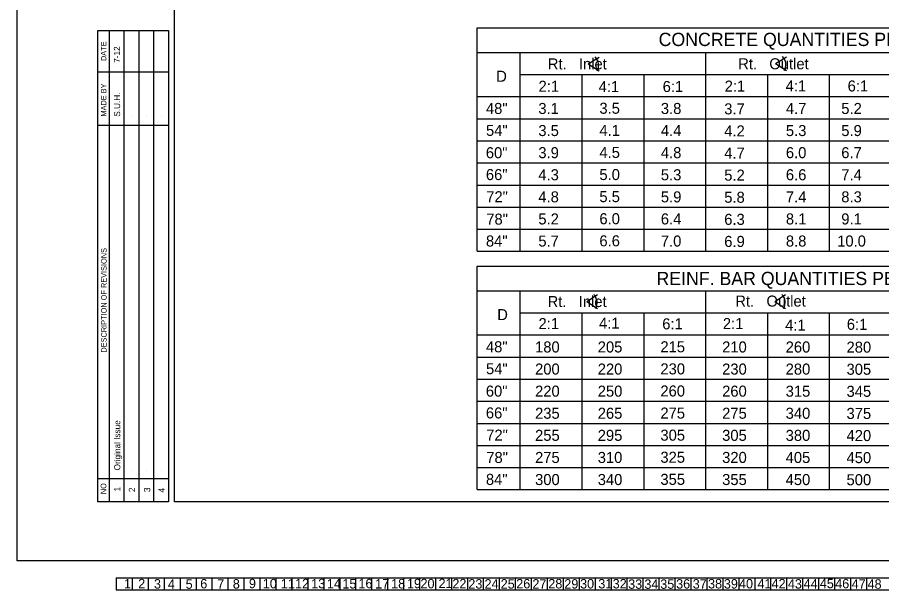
# Model space of a CAD drawing. Extents: x -0.08 to 2.83, y -0.03 to 1.92.
# Drawn here: x 0 to 0.917, y -0.031 to 0.576 of the extents above; entities that cross this region are included whole.
import ezdxf

# ---------------------------------------------------------------- set-up
doc = ezdxf.new("R2010")
doc.units = 0
for name, color, linetype in [('1', 7, 'Continuous'), ('10', 7, 'Continuous'), ('11', 7, 'Continuous'), ('12', 7, 'Continuous'), ('13', 7, 'Continuous'), ('14', 7, 'Continuous'), ('15', 7, 'Continuous'), ('16', 7, 'Continuous'), ('17', 7, 'Continuous'), ('18', 7, 'Continuous'), ('19', 7, 'Continuous'), ('2', 7, 'Continuous'), ('20', 7, 'Continuous'), ('21', 7, 'Continuous'), ('22', 7, 'Continuous'), ('23', 7, 'Continuous'), ('24', 7, 'Continuous'), ('25', 7, 'Continuous'), ('26', 7, 'Continuous'), ('27', 7, 'Continuous'), ('28', 7, 'Continuous'), ('29', 7, 'Continuous'), ('3', 7, 'Continuous'), ('30', 7, 'Continuous'), ('31', 7, 'Continuous'), ('32', 7, 'Continuous'), ('33', 7, 'Continuous'), ('34', 7, 'Continuous'), ('35', 7, 'Continuous'), ('36', 7, 'Continuous'), ('37', 7, 'Continuous'), ('38', 7, 'Continuous'), ('39', 7, 'Continuous'), ('4', 7, 'Continuous'), ('40', 7, 'Continuous'), ('41', 7, 'Continuous'), ('42', 7, 'Continuous'), ('43', 7, 'Continuous'), ('44', 7, 'Continuous'), ('45', 7, 'Continuous'), ('46', 7, 'Continuous'), ('47', 7, 'Continuous'), ('48', 7, 'Continuous'), ('5', 7, 'Continuous'), ('55', 7, 'Continuous'), ('57', 7, 'Continuous'), ('6', 7, 'Continuous'), ('62', 7, 'Continuous'), ('63', 7, 'Continuous'), ('7', 7, 'Continuous'), ('8', 7, 'Continuous'), ('9', 7, 'Continuous')]:
    doc.layers.add(name, color=color, linetype=linetype)

msp = doc.modelspace()

# ---------------------------------------------------------------- linework, layer by layer
at = {"layer": '55'}
for p, q in [((0.48802, 0.32823), (0.48802, 0.56521)), ((0.48802, 0.56521), (1.51802, 0.56521)), ((0.48802, 0.53916), (1.51802, 0.53916)), ((0.53364, 0.32823), (0.53364, 0.53916)), ((0.73052, 0.32823), (0.73052, 0.53916)), ((0.53364, 0.51573), (1.51802, 0.51573)), ((0.59927, 0.32823), (0.59927, 0.51573)), ((0.66489, 0.32823), (0.66489, 0.51573)), ((0.79614, 0.32823), (0.79614, 0.51573)), ((0.86177, 0.32823), (0.86177, 0.51573)), ((0.48802, 0.49229), (1.51802, 0.49229)), ((0.48802, 0.46885), (1.51802, 0.46885)), ((0.48802, 0.44541), (1.51802, 0.44541)), ((0.48802, 0.42198), (1.51802, 0.42198)), ((0.48802, 0.39854), (1.51802, 0.39854)), ((0.48802, 0.3751), (1.51802, 0.3751)), ((0.48802, 0.35166), (1.51802, 0.35166)), ((0.48802, 0.32823), (1.51802, 0.32823)), ((0.48801, 0.07539), (0.48801, 0.31237)), ((0.48801, 0.31237), (1.518, 0.31237)), ((0.48801, 0.28633), (1.518, 0.28633)), ((0.53363, 0.07539), (0.53363, 0.28633)), ((0.7305, 0.07539), (0.7305, 0.28633)), ((0.53363, 0.26289), (1.518, 0.26289)), ((0.59925, 0.07539), (0.59925, 0.26289)), ((0.66488, 0.07539), (0.66488, 0.26289)), ((0.79613, 0.07539), (0.79613, 0.26289)), ((0.86175, 0.07539), (0.86175, 0.26289)), ((0.48801, 0.23945), (1.518, 0.23945)), ((0.48801, 0.21601), (1.518, 0.21601)), ((0.48801, 0.19258), (1.518, 0.19258)), ((0.48801, 0.16914), (1.518, 0.16914)), ((0.48801, 0.1457), (1.518, 0.1457)), ((0.48801, 0.12226), (1.518, 0.12226)), ((0.48801, 0.09883), (1.518, 0.09883)), ((0.48801, 0.07539), (1.518, 0.07539))]:
    msp.add_line(p, q, dxfattribs=at)
at = {"layer": '57'}
for points in [[(0.60568, 0.52691), (0.61719, 0.53429)], [(0.80436, 0.5273), (0.81587, 0.53468)], [(0.60568, 0.52691), (0.61719, 0.51954)], [(0.80436, 0.5273), (0.81587, 0.51993)], [(0.60411, 0.27498), (0.61562, 0.28236)], [(0.80361, 0.27502), (0.81512, 0.28239)], [(0.60411, 0.27498), (0.61562, 0.26761)], [(0.80361, 0.27502), (0.81512, 0.26765)]]:
    msp.add_lwpolyline(points, dxfattribs=at)
for centre in [(0.60416, 0.52571), (0.80284, 0.5261), (0.60259, 0.27378), (0.80209, 0.27382)]:
    msp.add_arc(centre, 0.01252, 330.46976, 43.72317, dxfattribs=at)
at = {"layer": '62'}
for p, q in [((0.10585, 0.47101), (0.10585, 0.47101)), ((0.12188, 0.47101), (0.12188, 0.47101)), ((0.13719, 0.47101), (0.13719, 0.47101)), ((0.15252, 0.47101), (0.15252, 0.47101)), ((0.10603, 0.09579), (0.10603, 0.09579)), ((0.121, 0.09544), (0.121, 0.09544)), ((0.13668, 0.09544), (0.13668, 0.09544)), ((0.15304, 0.09579), (0.15304, 0.09579)), ((0.10494, -0.01804), (1.17174, -0.01804)), ((0.10494, -0.01804), (0.10494, -0.03074)), ((0.12188, -0.01804), (0.12188, -0.03074)), ((0.13881, -0.01804), (0.13881, -0.03074)), ((0.15574, -0.01804), (0.15574, -0.03074)), ((0.17267, -0.01804), (0.17267, -0.03074)), ((0.18961, -0.01804), (0.18961, -0.03074)), ((0.20654, -0.01804), (0.20654, -0.03074)), ((0.22348, -0.01804), (0.22348, -0.03074)), ((0.24041, -0.01804), (0.24041, -0.03074)), ((0.25734, -0.01804), (0.25734, -0.03074)), ((0.27427, -0.01804), (0.27427, -0.03074)), ((0.29121, -0.01804), (0.29121, -0.03074)), ((0.30814, -0.01804), (0.30814, -0.03074)), ((0.32508, -0.01804), (0.32508, -0.03074)), ((0.34201, -0.01804), (0.34201, -0.03074)), ((0.35894, -0.01804), (0.35894, -0.03074)), ((0.37588, -0.01804), (0.37588, -0.03074)), ((0.39281, -0.01804), (0.39281, -0.03074)), ((0.40974, -0.01804), (0.40974, -0.03074)), ((0.42668, -0.01804), (0.42668, -0.03074)), ((0.44361, -0.01804), (0.44361, -0.03074)), ((0.46054, -0.01804), (0.46054, -0.03074)), ((0.47748, -0.01804), (0.47748, -0.03074)), ((0.49441, -0.01804), (0.49441, -0.03074)), ((0.51134, -0.01804), (0.51134, -0.03074)), ((0.52828, -0.01804), (0.52828, -0.03074)), ((0.54521, -0.01804), (0.54521, -0.03074)), ((0.56214, -0.01804), (0.56214, -0.03074)), ((0.57908, -0.01804), (0.57908, -0.03074)), ((0.59601, -0.01804), (0.59601, -0.03074)), ((0.61294, -0.01804), (0.61294, -0.03074)), ((0.62988, -0.01804), (0.62988, -0.03074)), ((0.64681, -0.01804), (0.64681, -0.03074)), ((0.66374, -0.01804), (0.66374, -0.03074)), ((0.68068, -0.01804), (0.68068, -0.03074)), ((0.69761, -0.01804), (0.69761, -0.03074)), ((0.71454, -0.01804), (0.71454, -0.03074)), ((0.73147, -0.01804), (0.73147, -0.03074)), ((0.74841, -0.01804), (0.74841, -0.03074)), ((0.76534, -0.01804), (0.76534, -0.03074)), ((0.78228, -0.01804), (0.78228, -0.03074)), ((0.79921, -0.01804), (0.79921, -0.03074)), ((0.81614, -0.01804), (0.81614, -0.03074)), ((0.83308, -0.01804), (0.83308, -0.03074)), ((0.85001, -0.01804), (0.85001, -0.03074)), ((0.86694, -0.01804), (0.86694, -0.03074)), ((0.88388, -0.01804), (0.88388, -0.03074)), ((0.90081, -0.01804), (0.90081, -0.03074)), ((0.10494, -0.03074), (1.17174, -0.03074))]:
    msp.add_line(p, q, dxfattribs=at)
at = {"layer": '63'}
for p, q in [((0, 0), (0, 1.83333)), ((0.08543, 0.06244), (0.08543, 0.56244)), ((0.08543, 0.56244), (0.16043, 0.56244)), ((0.09792, 0.06244), (0.09792, 0.56244)), ((0.11353, 0.06259), (0.11353, 0.56244)), ((0.12914, 0.06275), (0.12914, 0.56244)), ((0.14474, 0.0629), (0.14474, 0.56244)), ((0.16043, 0.56244), (0.16043, 0.06244)), ((0.08543, 0.51859), (0.16043, 0.51859)), ((0.08543, 0.46218), (0.16043, 0.46218)), ((0.08543, 0.08707), (0.16043, 0.08707)), ((0.16043, 0.06244), (0.08543, 0.06244)), ((2.83333, 0), (0, 0))]:
    msp.add_line(p, q, dxfattribs=at)
msp.add_lwpolyline([(0.16668, 0.06244), (0.16668, 1.77077), (2.72918, 1.77077), (2.72918, 0.10411), (2.56251, 0.10411), (2.56251, 0.14578), (2.07387, 0.14578), (2.07387, 0.06244)], close=True, dxfattribs=at)

# ---------------------------------------------------------------- texts
at = {"layer": '1'}
msp.add_text('1', height=0.01, rotation=360, dxfattribs=at).set_placement((0.11316, -0.02944))
at = {"layer": '10'}
msp.add_text('10', height=0.01, rotation=360, dxfattribs=at).set_placement((0.26046, -0.02928))
at = {"layer": '11'}
msp.add_text('11', height=0.01, rotation=360, dxfattribs=at).set_placement((0.2796, -0.02937))
at = {"layer": '12'}
msp.add_text('12', height=0.01, rotation=360, dxfattribs=at).set_placement((0.29469, -0.02925))
at = {"layer": '13'}
msp.add_text('13', height=0.01, rotation=360, dxfattribs=at).set_placement((0.31181, -0.02928))
at = {"layer": '14'}
msp.add_text('14', height=0.01, rotation=360, dxfattribs=at).set_placement((0.32844, -0.02939))
at = {"layer": '15'}
msp.add_text('15', height=0.01, rotation=360, dxfattribs=at).set_placement((0.34488, -0.02946))
at = {"layer": '16'}
msp.add_text('16', height=0.01, rotation=360, dxfattribs=at).set_placement((0.3619, -0.02918))
at = {"layer": '17'}
msp.add_text('17', height=0.01, rotation=360, dxfattribs=at).set_placement((0.3797, -0.02946))
at = {"layer": '18'}
msp.add_text('18', height=0.01, rotation=360, dxfattribs=at).set_placement((0.39663, -0.02938))
at = {"layer": '19'}
msp.add_text('19', height=0.01, rotation=360, dxfattribs=at).set_placement((0.4134, -0.02918))
at = {"layer": '2'}
msp.add_text('2', height=0.01, rotation=360, dxfattribs=at).set_placement((0.12828, -0.02928))
at = {"layer": '20'}
msp.add_text('20', height=0.01, rotation=360, dxfattribs=at).set_placement((0.42774, -0.02926))
at = {"layer": '21'}
msp.add_text('21', height=0.01, rotation=360, dxfattribs=at).set_placement((0.44688, -0.02909))
at = {"layer": '22'}
msp.add_text('22', height=0.01, rotation=360, dxfattribs=at).set_placement((0.46158, -0.02929))
at = {"layer": '23'}
msp.add_text('23', height=0.01, rotation=360, dxfattribs=at).set_placement((0.47852, -0.02958))
at = {"layer": '24'}
msp.add_text('24', height=0.01, rotation=360, dxfattribs=at).set_placement((0.49576, -0.02958))
at = {"layer": '25'}
msp.add_text('25', height=0.01, rotation=360, dxfattribs=at).set_placement((0.51281, -0.02958))
at = {"layer": '26'}
msp.add_text('26', height=0.01, rotation=360, dxfattribs=at).set_placement((0.52931, -0.02936))
at = {"layer": '27'}
msp.add_text('27', height=0.01, rotation=360, dxfattribs=at).set_placement((0.54648, -0.02958))
at = {"layer": '28'}
msp.add_text('28', height=0.01, rotation=360, dxfattribs=at).set_placement((0.56333, -0.02938))
at = {"layer": '29'}
msp.add_text('29', height=0.01, rotation=360, dxfattribs=at).set_placement((0.58032, -0.02956))
at = {"layer": '3'}
msp.add_text('3', height=0.01, rotation=360, dxfattribs=at).set_placement((0.145, -0.02955))
at = {"layer": '30'}
msp.add_text('30', height=0.01, rotation=360, dxfattribs=at).set_placement((0.59706, -0.02946))
at = {"layer": '31'}
msp.add_text('31', height=0.01, rotation=360, dxfattribs=at).set_placement((0.61636, -0.02938))
at = {"layer": '32'}
msp.add_text('32', height=0.01, rotation=360, dxfattribs=at).set_placement((0.63163, -0.02938))
at = {"layer": '33'}
msp.add_text('33', height=0.01, rotation=360, dxfattribs=at).set_placement((0.64808, -0.02978))
at = {"layer": '34'}
msp.add_text('34', height=0.01, rotation=360, dxfattribs=at).set_placement((0.66527, -0.02978))
at = {"layer": '35'}
msp.add_text('35', height=0.01, rotation=360, dxfattribs=at).set_placement((0.68209, -0.02978))
at = {"layer": '36'}
msp.add_text('36', height=0.01, rotation=360, dxfattribs=at).set_placement((0.69895, -0.02958))
at = {"layer": '37'}
msp.add_text('37', height=0.01, rotation=360, dxfattribs=at).set_placement((0.71654, -0.02958))
at = {"layer": '38'}
msp.add_text('38', height=0.01, rotation=360, dxfattribs=at).set_placement((0.73281, -0.02938))
at = {"layer": '39'}
msp.add_text('39', height=0.01, rotation=360, dxfattribs=at).set_placement((0.74958, -0.0295))
at = {"layer": '4'}
msp.add_text('4', height=0.01, rotation=360, dxfattribs=at).set_placement((0.15973, -0.02984))
at = {"layer": '40'}
msp.add_text('40', height=0.01, rotation=360, dxfattribs=at).set_placement((0.76566, -0.02938))
at = {"layer": '41'}
msp.add_text('41', height=0.01, rotation=360, dxfattribs=at).set_placement((0.78528, -0.02938))
at = {"layer": '42'}
msp.add_text('42', height=0.01, rotation=360, dxfattribs=at).set_placement((0.8002, -0.0293))
at = {"layer": '43'}
msp.add_text('43', height=0.01, rotation=360, dxfattribs=at).set_placement((0.8175, -0.02958))
at = {"layer": '44'}
msp.add_text('44', height=0.01, rotation=360, dxfattribs=at).set_placement((0.83425, -0.02949))
at = {"layer": '45'}
msp.add_text('45', height=0.01, rotation=360, dxfattribs=at).set_placement((0.85139, -0.02918))
at = {"layer": '46'}
msp.add_text('46', height=0.01, rotation=360, dxfattribs=at).set_placement((0.8677, -0.02929))
at = {"layer": '47'}
msp.add_text('47', height=0.01, rotation=360, dxfattribs=at).set_placement((0.8852, -0.02958))
at = {"layer": '48'}
msp.add_text('48', height=0.01, rotation=360, dxfattribs=at).set_placement((0.90205, -0.02969))
at = {"layer": '5'}
msp.add_text('5', height=0.01, rotation=360, dxfattribs=at).set_placement((0.17858, -0.02977))
at = {"layer": '57'}
for s, height, p in [('CONCRETE QUANTITIES PER ADDITIONAL PIPE (C.Y.)', 0.0140625, (0.68037, 0.54595)), ('Rt.   Inlet', 0.0117, (0.56279, 0.52116)), ('Rt.   Outlet', 0.0117, (0.7648, 0.5213)), ('D', 0.0117, (0.50811, 0.50804)), ('2:1', 0.0117, (0.553, 0.49742)), ('4:1', 0.0117, (0.6168, 0.49709)), ('6:1', 0.0117, (0.68466, 0.49719)), ('2:1', 0.0117, (0.75047, 0.4976)), ('4:1', 0.0117, (0.81512, 0.49787)), ('6:1', 0.0117, (0.88089, 0.49777)), ('48"', 0.0117, (0.49719, 0.47393)), ('3.1', 0.011715, (0.55277, 0.47388)), ('3.5', 0.011715, (0.61754, 0.4741)), ('3.8', 0.011715, (0.68275, 0.47388)), ('3.7', 0.011715, (0.74999, 0.47346)), ('4.7', 0.011715, (0.81537, 0.47388)), (' 5.2', 0.011715, (0.86979, 0.47388)), ('54"', 0.0117, (0.49725, 0.45065)), ('3.5', 0.011715, (0.55277, 0.45045)), ('4.1', 0.011715, (0.61754, 0.45066)), ('4.4', 0.011715, (0.68275, 0.45045)), ('4.2', 0.011715, (0.74999, 0.45003)), ('5.3', 0.011715, (0.81537, 0.45045)), (' 5.9', 0.011715, (0.86979, 0.45045)), ('60"', 0.0117, (0.49708, 0.42692)), ('3.9', 0.011715, (0.55277, 0.42701)), ('4.5', 0.011715, (0.61754, 0.42723)), ('4.8', 0.011715, (0.68275, 0.42701)), ('4.7', 0.011715, (0.74999, 0.42659)), ('6.0', 0.011715, (0.81537, 0.42701)), (' 6.7', 0.011715, (0.86979, 0.42701)), ('66"', 0.0117, (0.49713, 0.40377)), ('4.3', 0.011715, (0.55277, 0.40357)), ('5.0', 0.011715, (0.61754, 0.40379)), ('5.3', 0.011715, (0.68275, 0.40357)), ('5.2', 0.011715, (0.74999, 0.40315)), ('6.6', 0.011715, (0.81537, 0.40357)), (' 7.4', 0.011715, (0.86979, 0.40357)), ('72"', 0.0117, (0.49749, 0.38025)), ('4.8', 0.011715, (0.55277, 0.38013)), ('5.5', 0.011715, (0.61754, 0.38035)), ('5.9', 0.011715, (0.68275, 0.38013)), ('5.8', 0.011715, (0.74999, 0.37971)), ('7.4', 0.011715, (0.81537, 0.38013)), (' 8.3', 0.011715, (0.86979, 0.38013)), ('78"', 0.0117, (0.49755, 0.35651)), ('5.2', 0.011715, (0.55277, 0.3567)), ('6.0', 0.011715, (0.61754, 0.35691)), ('6.4', 0.011715, (0.68275, 0.3567)), ('6.3', 0.011715, (0.74999, 0.35628)), ('8.1', 0.011715, (0.81537, 0.3567)), (' 9.1', 0.011715, (0.86979, 0.3567)), ('84"', 0.0117, (0.49718, 0.3333)), ('5.7', 0.011715, (0.55277, 0.33326)), ('6.6', 0.011715, (0.61754, 0.33348)), ('7.0', 0.011715, (0.68275, 0.33326)), ('6.9', 0.011715, (0.74999, 0.33284)), ('8.8', 0.011715, (0.81537, 0.33326)), ('10.0', 0.011715, (0.86979, 0.33326)), ('REINF. BAR QUANTITIES PER ADDITIONAL PIPE (Lbs.)', 0.0140625, (0.67804, 0.29238)), ('Rt.   Inlet', 0.0117, (0.56262, 0.26909)), ('Rt.   Outlet', 0.0117, (0.76172, 0.26957)), ('D', 0.0117, (0.50919, 0.2552)), ('2:1', 0.0117, (0.55298, 0.24565)), ('4:1', 0.0117, (0.61719, 0.24615)), ('6:1', 0.0117, (0.68425, 0.24543)), ('2:1', 0.0117, (0.74853, 0.24571)), ('6:1', 0.0117, (0.87999, 0.2449)), ('4:1', 0.0117, (0.81461, 0.24414)), ('48"', 0.0117, (0.49717, 0.22109)), ('180', 0.011715, (0.5493, 0.2209)), ('205', 0.011715, (0.61578, 0.2209)), ('215', 0.011715, (0.68226, 0.22108)), ('210', 0.011715, (0.74775, 0.2209)), ('260', 0.011715, (0.81514, 0.22086)), ('280', 0.011715, (0.87972, 0.2207)), ('54"', 0.0117, (0.49724, 0.19781)), ('200', 0.011715, (0.5493, 0.19746)), ('220', 0.011715, (0.61578, 0.19746)), ('230', 0.011715, (0.68226, 0.19765)), ('230', 0.011715, (0.74775, 0.19746)), ('280', 0.011715, (0.81514, 0.19742)), ('305', 0.011715, (0.87972, 0.19726)), ('60"', 0.0117, (0.49707, 0.17408)), ('220', 0.011715, (0.5493, 0.17402)), ('250', 0.011715, (0.61578, 0.17402)), ('260', 0.011715, (0.68226, 0.17421)), ('260', 0.011715, (0.74775, 0.17402)), ('315', 0.011715, (0.81514, 0.17398)), ('345', 0.011715, (0.87972, 0.17383)), ('66"', 0.0117, (0.49711, 0.15094)), ('235', 0.011715, (0.5493, 0.15058)), ('265', 0.011715, (0.61578, 0.15058)), ('275', 0.011715, (0.68226, 0.15077)), ('275', 0.011715, (0.74775, 0.15058)), ('340', 0.011715, (0.81514, 0.15055)), ('375', 0.011715, (0.87972, 0.15039)), ('72"', 0.0117, (0.49747, 0.12742)), ('255', 0.011715, (0.5493, 0.12715)), ('295', 0.011715, (0.61578, 0.12715)), ('305', 0.011715, (0.68226, 0.12733)), ('305', 0.011715, (0.74775, 0.12715)), ('380', 0.011715, (0.81514, 0.12711)), ('420', 0.011715, (0.87972, 0.12695)), ('78"', 0.0117, (0.49754, 0.10367)), ('275', 0.011715, (0.5493, 0.10371)), ('310', 0.011715, (0.61578, 0.10371)), ('325', 0.011715, (0.68226, 0.1039)), ('320', 0.011715, (0.74775, 0.10371)), ('405', 0.011715, (0.81514, 0.10367)), ('450', 0.011715, (0.87972, 0.10351)), ('84"', 0.0117, (0.49716, 0.08047)), ('300', 0.011715, (0.5493, 0.08027)), ('340', 0.011715, (0.61578, 0.08027)), ('355', 0.011715, (0.68226, 0.08046)), ('355', 0.011715, (0.74775, 0.08027)), ('450', 0.011715, (0.81514, 0.08023)), ('500', 0.011715, (0.87972, 0.08008))]:
    msp.add_text(s, height=height, dxfattribs=at).set_placement(p)
at = {"layer": '6'}
msp.add_text('6', height=0.01, rotation=360, dxfattribs=at).set_placement((0.19409, -0.02938))
at = {"layer": '62'}
for s, height, p in [(' 7-12', 0.006508, (0.10896, 0.52578)), ('S.U.H.  ', 0.006508, (0.1091, 0.47101)), ('Original Issue                                                   ', 0.0065084, (0.10928, 0.09579))]:
    msp.add_text(s, height=height, rotation=90, dxfattribs=at).set_placement(p)
at = {"layer": '63'}
for s, height, p in [('DATE', 0.005833, (0.09454, 0.53)), ('MADE BY', 0.005833, (0.09454, 0.47113)), ('DESCRIPTION OF REVISIONS', 0.0058333, (0.09477, 0.22076)), ('NO', 0.005833, (0.09439, 0.07059)), ('1', 0.00667, (0.10936, 0.0735)), ('2', 0.00667, (0.12503, 0.07272)), ('3', 0.00667, (0.14105, 0.07272)), ('4', 0.00667, (0.15638, 0.07237))]:
    msp.add_text(s, height=height, rotation=90, dxfattribs=at).set_placement(p)
at = {"layer": '7'}
msp.add_text('7', height=0.01, rotation=360, dxfattribs=at).set_placement((0.21211, -0.02964))
at = {"layer": '8'}
msp.add_text('8', height=0.01, rotation=360, dxfattribs=at).set_placement((0.22865, -0.02958))
at = {"layer": '9'}
msp.add_text('9', height=0.01, rotation=360, dxfattribs=at).set_placement((0.24573, -0.02921))

doc.saveas('drawing.dxf')
